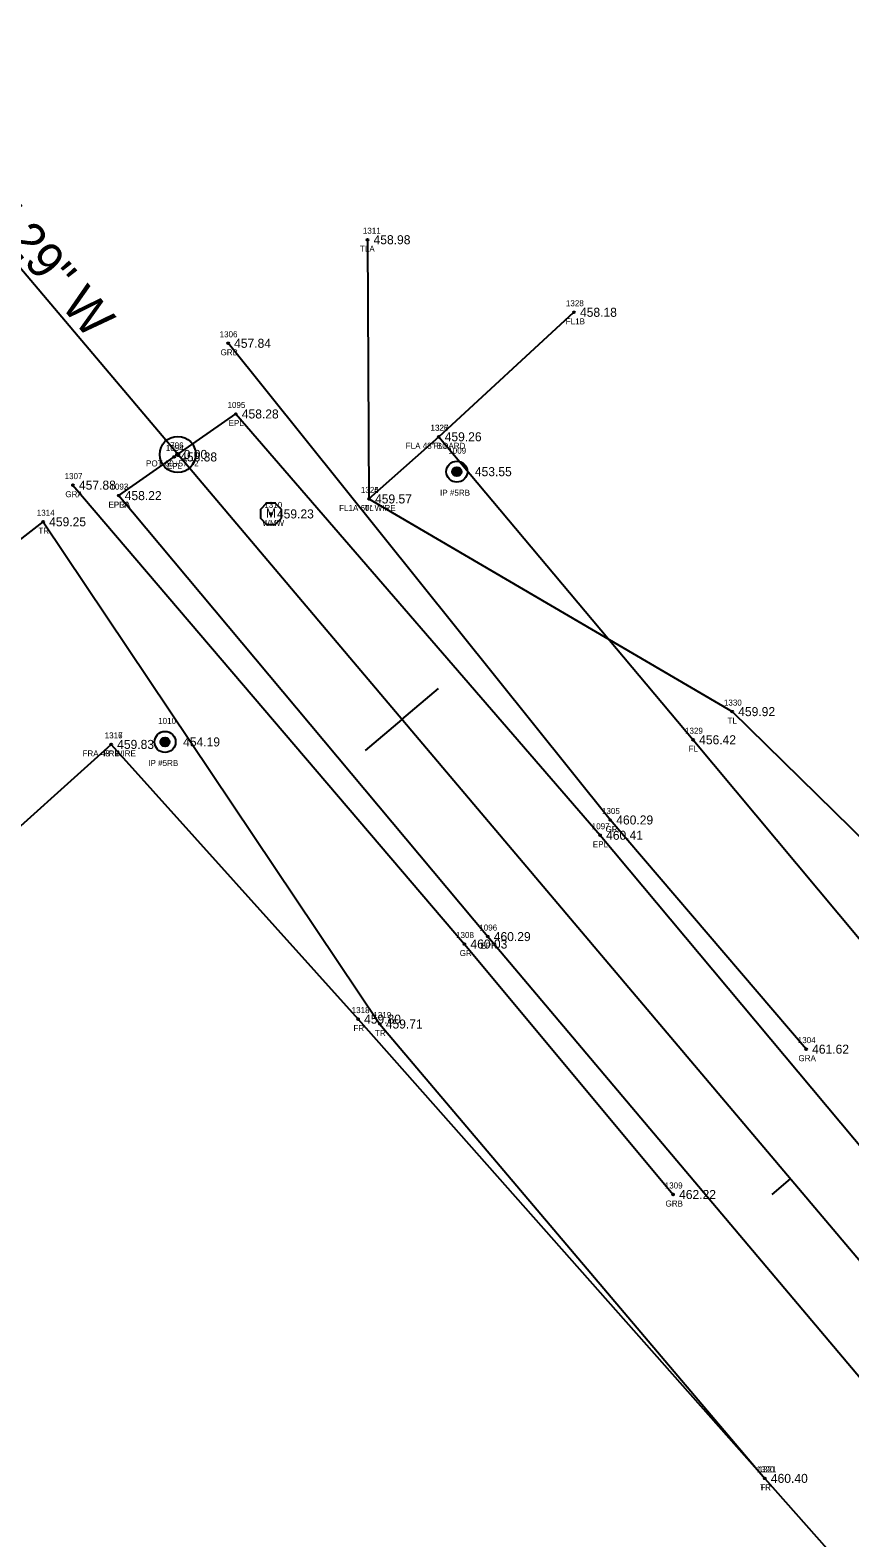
# Model space of a CAD drawing. Extents: x 1745838 to 1751416, y 649214 to 655806.
# Drawn here: x 1749236.5 to 1749372.8, y 651090.3 to 651340.9 of the extents above; entities that cross this region are included whole.
import ezdxf

# ---------------------------------------------------------------- set-up
doc = ezdxf.new("R2010")
doc.units = 0
for name, color, linetype in [('RD_EX_DV_Prop_txCode', 7, 'Continuous'), ('RD_EX_DV_PropPin', 7, 'Continuous'), ('RD_EX_Fence_Other', 7, 'Continuous'), ('RD_EX_Fence_Other_txCode', 7, 'Continuous'), ('RD_EX_GuardRail', 7, 'Continuous'), ('RD_EX_GuardRail_txCode', 7, 'Continuous'), ('RD_EX_Misc_txCode', 7, 'Continuous'), ('RD_EX_Road', 7, 'Continuous'), ('RD_EX_Road_txCode', 7, 'Continuous'), ('RD_EX_TX_DV_Prop_ELEV', 7, 'Continuous'), ('RD_EX_TX_Fence_Other_ELEV', 7, 'Continuous'), ('RD_EX_TX_GuardRail_ELEV', 7, 'Continuous'), ('RD_EX_TX_Misc_ELEV', 7, 'Continuous'), ('RD_EX_TX_Road_ELEV', 7, 'Continuous'), ('RD_EX_TX_VEG_ELEV', 7, 'Continuous'), ('RD_EX_UT', 7, 'Continuous'), ('RD_EX_VEG', 7, 'Continuous'), ('RD_EX_VEG_txCode', 7, 'Continuous'), ('RD_HC_Cl', 7, 'Continuous'), ('RD_HC_Data', 7, 'Continuous'), ('RD_HC_Data_Tic', 7, 'Continuous'), ('RD_HC_Survey_ELEV', 7, 'Continuous'), ('RD_HC_txCode', 7, 'Continuous'), ('RD_SMD_Locator', 7, 'Continuous')]:
    doc.layers.add(name, color=color, linetype=linetype)

msp = doc.modelspace()

# ---------------------------------------------------------------- linework, layer by layer
at = {"layer": 'RD_EX_DV_PropPin'}
for p, q in [((1749306.72, 651267.28), (1749306.72, 651267.67)), ((1749306.76, 651267.18), (1749306.76, 651267.77)), ((1749306.79, 651267.11), (1749306.79, 651267.84)), ((1749306.83, 651267.05), (1749306.83, 651267.9)), ((1749306.86, 651267), (1749306.86, 651267.95)), ((1749306.9, 651266.96), (1749306.9, 651267.99)), ((1749306.93, 651266.92), (1749306.93, 651268.03)), ((1749306.97, 651266.89), (1749306.97, 651268.06)), ((1749307, 651266.87), (1749307, 651268.08)), ((1749307.04, 651266.84), (1749307.04, 651268.11)), ((1749307.07, 651266.82), (1749307.07, 651268.13)), ((1749307.11, 651266.8), (1749307.11, 651268.15)), ((1749307.14, 651266.78), (1749307.14, 651268.17)), ((1749307.18, 651266.77), (1749307.18, 651268.18)), ((1749307.21, 651266.75), (1749307.21, 651268.2)), ((1749307.25, 651266.74), (1749307.25, 651268.21)), ((1749307.28, 651266.73), (1749307.28, 651268.22)), ((1749307.32, 651266.73), (1749307.32, 651268.22)), ((1749307.35, 651266.72), (1749307.35, 651268.23)), ((1749307.39, 651266.72), (1749307.39, 651268.23)), ((1749307.42, 651266.71), (1749307.42, 651268.24)), ((1749307.46, 651266.71), (1749307.46, 651268.24)), ((1749307.49, 651266.71), (1749307.49, 651268.24)), ((1749307.53, 651266.72), (1749307.53, 651268.23)), ((1749307.56, 651266.72), (1749307.56, 651268.23)), ((1749307.6, 651266.73), (1749307.6, 651268.22)), ((1749307.63, 651266.73), (1749307.63, 651268.22)), ((1749307.67, 651266.74), (1749307.67, 651268.21)), ((1749307.7, 651266.75), (1749307.7, 651268.2)), ((1749307.74, 651266.77), (1749307.74, 651268.18)), ((1749307.77, 651266.78), (1749307.77, 651268.17)), ((1749307.81, 651266.8), (1749307.81, 651268.15)), ((1749307.84, 651266.82), (1749307.84, 651268.13)), ((1749307.88, 651266.84), (1749307.88, 651268.11)), ((1749307.91, 651266.87), (1749307.91, 651268.08)), ((1749307.95, 651266.89), (1749307.95, 651268.06)), ((1749307.98, 651266.92), (1749307.98, 651268.03)), ((1749308.02, 651266.96), (1749308.02, 651267.99)), ((1749308.05, 651267), (1749308.05, 651267.95)), ((1749308.09, 651267.05), (1749308.09, 651267.9)), ((1749308.12, 651267.11), (1749308.12, 651267.84)), ((1749308.16, 651267.18), (1749308.16, 651267.77)), ((1749308.19, 651267.28), (1749308.19, 651267.67)), ((1749258.2, 651222.35), (1749258.2, 651222.74)), ((1749258.24, 651222.25), (1749258.24, 651222.85)), ((1749258.27, 651222.18), (1749258.27, 651222.92)), ((1749258.31, 651222.12), (1749258.31, 651222.98)), ((1749258.34, 651222.07), (1749258.34, 651223.02)), ((1749258.38, 651222.03), (1749258.38, 651223.06)), ((1749258.41, 651222), (1749258.41, 651223.1)), ((1749258.45, 651221.97), (1749258.45, 651223.13)), ((1749258.48, 651221.94), (1749258.48, 651223.16)), ((1749258.52, 651221.91), (1749258.52, 651223.18)), ((1749258.55, 651221.89), (1749258.55, 651223.21)), ((1749258.59, 651221.87), (1749258.59, 651223.22)), ((1749258.62, 651221.86), (1749258.62, 651223.24)), ((1749258.66, 651221.84), (1749258.66, 651223.26)), ((1749258.69, 651221.83), (1749258.69, 651223.27)), ((1749258.73, 651221.82), (1749258.73, 651223.28)), ((1749258.76, 651221.81), (1749258.76, 651223.29)), ((1749258.8, 651221.8), (1749258.8, 651223.3)), ((1749258.83, 651221.79), (1749258.83, 651223.3)), ((1749258.87, 651221.79), (1749258.87, 651223.31)), ((1749258.9, 651221.79), (1749258.9, 651223.31)), ((1749258.94, 651221.79), (1749258.94, 651223.31)), ((1749258.97, 651221.79), (1749258.97, 651223.31)), ((1749259.01, 651221.79), (1749259.01, 651223.31)), ((1749259.04, 651221.79), (1749259.04, 651223.3)), ((1749259.08, 651221.8), (1749259.08, 651223.3)), ((1749259.11, 651221.81), (1749259.11, 651223.29)), ((1749259.15, 651221.82), (1749259.15, 651223.28)), ((1749259.18, 651221.83), (1749259.18, 651223.27)), ((1749259.22, 651221.84), (1749259.22, 651223.26)), ((1749259.25, 651221.86), (1749259.25, 651223.24)), ((1749259.29, 651221.87), (1749259.29, 651223.22)), ((1749259.32, 651221.89), (1749259.32, 651223.21)), ((1749259.36, 651221.91), (1749259.36, 651223.18)), ((1749259.39, 651221.94), (1749259.39, 651223.16)), ((1749259.43, 651221.97), (1749259.43, 651223.13)), ((1749259.46, 651222), (1749259.46, 651223.1)), ((1749259.5, 651222.03), (1749259.5, 651223.06)), ((1749259.53, 651222.07), (1749259.53, 651223.02)), ((1749259.57, 651222.12), (1749259.57, 651222.98)), ((1749259.6, 651222.18), (1749259.6, 651222.92)), ((1749259.64, 651222.25), (1749259.64, 651222.85)), ((1749259.67, 651222.35), (1749259.67, 651222.74))]:
    msp.add_line(p, q, dxfattribs=at)
for centre, radius in [((1749307.46, 651267.47), 1.75), ((1749307.46, 651267.47), 0.761), ((1749258.94, 651222.55), 1.75), ((1749258.94, 651222.55), 0.761)]:
    msp.add_circle(centre, radius, dxfattribs=at)
at = {"layer": 'RD_EX_Fence_Other'}
for points in [[(1749292.85, 651262.94), (1749304.44, 651273.27), (1749326.94, 651293.96)], [(1749304.44, 651273.27), (1749346.75, 651222.91), (1749412.38, 651144.42), (1749477.88, 651069.69), (1749511.15, 651032.4), (1749545.77, 650993.77), (1749578.55, 650957.25), (1749610.1, 650921.66), (1749642.49, 650885.46)], [(1749228.24, 651202.64), (1749249.97, 651222.14), (1749249.97, 651222.14), (1749291.03, 651176.48), (1749358.68, 651100.15), (1749424.34, 651025.98), (1749461.84, 650986.11), (1749495.25, 650947.39), (1749527.17, 650911.79), (1749559.6, 650874.95), (1749594.11, 650836.92), (1749630.2, 650798.28), (1749673.95, 650750.13)]]:
    msp.add_lwpolyline(points, dxfattribs=at)
at = {"layer": 'RD_EX_GuardRail'}
for points in [[(1749365.54, 651171.49), (1749332.97, 651209.58), (1749269.42, 651288.81)], [(1749243.62, 651265.23), (1749308.72, 651188.96), (1749343.42, 651147.33)]]:
    msp.add_lwpolyline(points, dxfattribs=at)
at = {"layer": 'RD_EX_Road'}
for points in [[(1749251.23, 651263.49), (1749260.45, 651269.92), (1749270.7, 651277.06), (1749331.28, 651207.04), (1749394.89, 651131.1), (1749464.1, 651050.42), (1749492.73, 651017.57), (1749527.83, 650977.98), (1749561.42, 650940.92), (1749594.62, 650904.59), (1749626.83, 650869.89), (1749663.01, 650831.46)], [(1749251.23, 651263.49), (1749312.6, 651190.2), (1749376.08, 651115.04), (1749444.52, 651034.93), (1749474.1, 651000.8), (1749509.41, 650961.27), (1749542.74, 650924.34), (1749575.97, 650888.1), (1749609.21, 650852.55), (1749645.22, 650814.16)]]:
    msp.add_lwpolyline(points, dxfattribs=at)
at = {"layer": 'RD_EX_UT'}
msp.add_lwpolyline([(1749278.3, 651259.73), (1749278.3, 651261.18), (1749277.27, 651262.21), (1749275.82, 651262.21), (1749274.79, 651261.18), (1749274.79, 651259.73), (1749275.82, 651258.7), (1749277.27, 651258.7)], close=True, dxfattribs=at)
msp.add_circle((1749276.54, 651260.45), 0.15, dxfattribs=at)
at = {"layer": 'RD_EX_VEG'}
for points in [[(1749292.61, 651306.02), (1749292.85, 651262.94), (1749353.25, 651227.59), (1749426.65, 651155.69), (1749490.1, 651079.31), (1749524.79, 651042.62), (1749567.49, 651005.56), (1749592.48, 650970.09), (1749623.12, 650933.84), (1749658.1, 650906.44)], [(1749178.77, 651203.37), (1749202.73, 651231.24), (1749238.66, 651259.14), (1749294.64, 651175.67), (1749358.68, 651100.15), (1749424.34, 651025.98), (1749461.84, 650986.11), (1749495.25, 650947.39), (1749527.17, 650911.79), (1749559.6, 650874.95), (1749594.11, 650836.92), (1749630.2, 650798.28), (1749696.62, 650725.69)]]:
    msp.add_lwpolyline(points, dxfattribs=at)
at = {"layer": 'RD_HC_Cl'}
msp.add_line((1749546.44, 650932.91), (1748908.1, 651687.62), dxfattribs=at)
at = {"layer": 'RD_HC_Data'}
for radius in [3, 0.282]:
    msp.add_circle((1749261.04, 651270.34), radius, dxfattribs=at)
at = {"layer": 'RD_HC_Data_Tic'}
for p, q in [((1749298.32, 651226.27), (1749304.42, 651231.43)), ((1749298.32, 651226.27), (1749292.21, 651221.1)), ((1749362.89, 651149.92), (1749359.84, 651147.33))]:
    msp.add_line(p, q, dxfattribs=at)
at = {"layer": 'RD_SMD_Locator'}
for centre in [(1749292.61, 651306.02), (1749326.94, 651293.96), (1749269.42, 651288.81), (1749270.7, 651277.06), (1749304.44, 651273.27), (1749304.44, 651273.27), (1749260.45, 651269.92), (1749261.04, 651270.34), (1749307.46, 651267.47), (1749243.62, 651265.23), (1749251.23, 651263.49), (1749251.23, 651263.49), (1749292.85, 651262.94), (1749292.85, 651262.94), (1749238.66, 651259.14), (1749353.25, 651227.59), (1749249.97, 651222.14), (1749249.97, 651222.14), (1749258.94, 651222.55), (1749346.75, 651222.91), (1749332.97, 651209.58), (1749331.28, 651207.04), (1749312.6, 651190.2), (1749308.72, 651188.96), (1749291.03, 651176.48), (1749294.64, 651175.67), (1749365.54, 651171.49), (1749343.42, 651147.33), (1749358.68, 651100.15), (1749358.68, 651100.15)]:
    msp.add_circle(centre, 0.15, dxfattribs=at)

# ---------------------------------------------------------------- texts
at = {"layer": 'RD_EX_DV_Prop_txCode'}
for s, p in [('1009', (1749306.03, 651270.47)), ('IP #5RB', (1749304.67, 651263.47)), ('1010', (1749257.79, 651225.55)), ('IP #5RB', (1749256.15, 651218.55))]:
    msp.add_text(s, height=1, dxfattribs=at).set_placement(p)
at = {"layer": 'RD_EX_Fence_Other_txCode'}
for s, p in [('1328', (1749325.59, 651294.96)), ('FL1B', (1749325.57, 651291.96)), ('1326', (1749303.07, 651274.27)), ('1327', (1749303.1, 651274.27)), ('FLA 48" BOARD', (1749298.96, 651271.27)), ('FL1', (1749303.55, 651271.27)), ('1324', (1749291.5, 651263.94)), ('FL1A 60" WIRE', (1749287.88, 651260.94)), ('1329', (1749345.4, 651223.91)), ('1316', (1749248.89, 651223.14)), ('1317', (1749248.91, 651223.14)), ('FL', (1749346.01, 651220.91)), ('FRA 48" WIRE', (1749245.21, 651220.14)), ('FRB', (1749248.74, 651220.14)), ('1318', (1749289.97, 651177.48)), ('FR', (1749290.27, 651174.48)), ('1321', (1749357.62, 651101.15)), ('FR', (1749357.93, 651098.15))]:
    msp.add_text(s, height=1, dxfattribs=at).set_placement(p)
at = {"layer": 'RD_EX_GuardRail_txCode'}
for s, p in [('1306', (1749268.01, 651289.81)), ('GRB', (1749268.16, 651286.81)), ('1307', (1749242.23, 651266.23)), ('GRA', (1749242.35, 651263.23)), ('1305', (1749331.59, 651210.58)), ('GR', (1749332.19, 651207.58)), ('1308', (1749307.33, 651189.96)), ('GR', (1749307.94, 651186.96)), ('1304', (1749364.15, 651172.49)), ('GRA', (1749364.27, 651169.49)), ('1309', (1749342.03, 651148.33)), ('GRB', (1749342.16, 651145.33))]:
    msp.add_text(s, height=1, dxfattribs=at).set_placement(p)
at = {"layer": 'RD_EX_Misc_txCode'}
for s, p in [('1310', (1749275.44, 651261.45)), ('WMW', (1749275.1, 651258.45))]:
    msp.add_text(s, height=1, dxfattribs=at).set_placement(p)
at = {"layer": 'RD_EX_Road_txCode'}
for s, p in [('1095', (1749269.32, 651278.06)), ('EPL', (1749269.5, 651275.06)), ('1094', (1749259.06, 651270.92)), ('EPL', (1749259.24, 651267.92)), ('1092', (1749249.85, 651264.49)), ('1093', (1749249.85, 651264.49)), ('EPRA', (1749249.51, 651261.49)), ('EPLA', (1749249.54, 651261.49)), ('1097', (1749329.89, 651208.04)), ('EPL', (1749330.07, 651205.04)), ('1096', (1749311.19, 651191.2)), ('EPR', (1749311.37, 651188.2))]:
    msp.add_text(s, height=1, dxfattribs=at).set_placement(p)
at = {"layer": 'RD_EX_TX_DV_Prop_ELEV'}
for s, p in [('453.55', (1749310.46, 651266.72)), ('454.19', (1749261.94, 651221.8))]:
    msp.add_text(s, height=1.5, dxfattribs=at).set_placement(p)
at = {"layer": 'RD_EX_TX_Fence_Other_ELEV'}
for s, p in [('458.18', (1749327.94, 651293.21)), ('459.26', (1749305.44, 651272.52)), ('459.26', (1749305.44, 651272.52)), ('459.57', (1749293.85, 651262.19)), ('459.83', (1749250.97, 651221.39)), ('459.83', (1749250.97, 651221.39)), ('456.42', (1749347.75, 651222.16)), ('459.80', (1749292.03, 651175.73)), ('460.40', (1749359.68, 651099.4))]:
    msp.add_text(s, height=1.5, dxfattribs=at).set_placement(p)
at = {"layer": 'RD_EX_TX_GuardRail_ELEV'}
for s, p in [('457.84', (1749270.42, 651288.06)), ('457.88', (1749244.62, 651264.48)), ('460.29', (1749333.97, 651208.83)), ('460.03', (1749309.72, 651188.21)), ('461.62', (1749366.54, 651170.74)), ('462.22', (1749344.42, 651146.58))]:
    msp.add_text(s, height=1.5, dxfattribs=at).set_placement(p)
at = {"layer": 'RD_EX_TX_Misc_ELEV'}
msp.add_text('459.23', height=1.5, dxfattribs=at).set_placement((1749277.54, 651259.7))
at = {"layer": 'RD_EX_TX_Road_ELEV'}
for s, p in [('458.28', (1749271.7, 651276.31)), ('458.38', (1749261.45, 651269.17)), ('458.22', (1749252.23, 651262.74)), ('458.22', (1749252.23, 651262.74)), ('460.41', (1749332.28, 651206.29)), ('460.29', (1749313.6, 651189.45))]:
    msp.add_text(s, height=1.5, dxfattribs=at).set_placement(p)
at = {"layer": 'RD_EX_TX_VEG_ELEV'}
for s, p in [('458.98', (1749293.61, 651305.27)), ('459.57', (1749293.85, 651262.19)), ('459.25', (1749239.66, 651258.39)), ('459.92', (1749354.25, 651226.84)), ('459.71', (1749295.64, 651174.92)), ('460.40', (1749359.68, 651099.4))]:
    msp.add_text(s, height=1.5, dxfattribs=at).set_placement(p)
at = {"layer": 'RD_EX_UT'}
msp.add_text('M', height=1.5, dxfattribs=at).set_placement((1749275.71, 651259.85))
at = {"layer": 'RD_EX_VEG_txCode'}
for s, p in [('1311', (1749291.83, 651307.02)), ('TLA', (1749291.35, 651304.02)), ('1325', (1749291.5, 651263.94)), ('TL', (1749292.08, 651260.94)), ('1314', (1749237.6, 651260.14)), ('TR', (1749237.87, 651257.14)), ('1330', (1749351.87, 651228.59)), ('TL', (1749352.48, 651225.59)), ('1319', (1749293.58, 651176.67)), ('TR', (1749293.84, 651173.67)), ('1320', (1749357.3, 651101.15)), ('TR', (1749357.89, 651098.15))]:
    msp.add_text(s, height=1, dxfattribs=at).set_placement(p)
at = {"layer": 'RD_HC_Data'}
msp.add_text('N 40%%d 13\' 29" W', height=6, rotation=310.2248, dxfattribs=at).set_placement((1749209.74, 651332.54))
at = {"layer": 'RD_HC_Survey_ELEV'}
msp.add_text('0.00', height=1.5, dxfattribs=at).set_placement((1749262.04, 651269.59))
at = {"layer": 'RD_HC_txCode'}
for s, p in [('706', (1749259.79, 651271.34)), ('POT 60+57.72', (1749255.78, 651268.34))]:
    msp.add_text(s, height=1, dxfattribs=at).set_placement(p)

doc.saveas('drawing.dxf')
